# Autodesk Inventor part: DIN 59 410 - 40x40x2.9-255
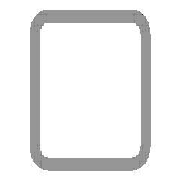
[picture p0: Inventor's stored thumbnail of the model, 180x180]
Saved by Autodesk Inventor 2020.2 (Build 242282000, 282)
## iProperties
Manager: www.cadconsulting.pl
Company: Fabian Stasiak CAD Consulting
_CCFamilyMember: 10
_CCFamilyDisplayName: DIN 59410 (Kwadrat) - Rurki stalowe o przekroju kwadratowym formowane na gorąco
_FrameMemberDoc: Frame Member File
_Version: 15.0.0
_GetPNFromCC: 1
Created: 2015-01
Part Number: DIN 59 410 - 40x40x2.9-255
Material: Stal, miękka
Description: Rurki stalowe o przekroju kwadratowym formowane na gorąco
Document SubType Name: Modellieren
Standard: DIN
Designer: F.Stasiak
Standards Organization: DIN
Language: pl-PL
Size Designation: 40x40x2.9
Categories: <MemberInstance><Categories><Category DisplayName="Kształtowniki konstrukcyjne" InternalName="089c4875-fa83-4c05-b084-43b9cc11f5ed" Mnemonic="GRDR"><CategoryPar
Stock Number: 40x40x2.9
Density: 7.85 g/cm^3
Appearance: Częściowo polerowana
Mass: 818.12 g
Surface Area: 726.927 cm^2
Volume: 104.219 cm^3
Catalog Web Link: www.expertbooks.pl
IsCustomPart: 1
G_L: 255,000 mm
G_W: 40,000 mm
G_H: 40,000 mm
+9123B27D-AADA-494F-B97F-F92D2769A03D+CUTDETAIL1: Wytnij
+8B292EAE-3E6B-4FBF-B364-8C41014E1728+CUTDETAIL2: Wytnij
Author: F.Stasiak
Subject: Zbiór ćwiczeń. Autodesk Inventor 2020. Kurs Professional
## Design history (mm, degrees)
node "Płaszczyzna początkowa"
node "Płaszczyzna końcowa"
sketch "Szkic"
  geometry: L1 (-14.2, 20)-(14.2, 20); L2 (20, 14.2)-(20, -14.2); L3 (14.2, -20)-(-14.2, -20); L4 (-20, -14.2)-(-20, 14.2); L5 (-29.682, 0)-(29.682, 0) reference; L6 (0, -29.682)-(0, 29.682) reference; L7 (-14.2, 17.1)-(14.2, 17.1); L8 (17.1, 14.2)-(17.1, -14.2); L9 (14.2, -17.1)-(-14.2, -17.1); L10 (-17.1, -14.2)-(-17.1, 14.2); A1 r 5.8 centre (-14.2, 14.2) between (-14.2, 20) and (-20, 14.2); A2 r 5.8 centre (14.2, 14.2) between (20, 14.2) and (14.2, 20); A3 r 5.8 centre (14.2, -14.2) between (14.2, -20) and (20, -14.2); A4 r 5.8 centre (-14.2, -14.2) between (-20, -14.2) and (-14.2, -20); A5 r 2.9 centre (-14.2, 14.2) between (-14.2, 17.1) and (-17.1, 14.2); A6 r 2.9 centre (14.2, 14.2) between (17.1, 14.2) and (14.2, 17.1); A7 r 2.9 centre (14.2, -14.2) between (14.2, -17.1) and (17.1, -14.2); A8 r 2.9 centre (-14.2, -14.2) between (-17.1, -14.2) and (-14.2, -17.1); 3 further points
  constraints: 16 end point, 16 point on circle, 8 centre point, 8 tangent, 6 point on line, 4 parallel, 3 equal radius, 3 perpendicular, 1 horizontal, 7 other
  dimensions: "b" = 40 distance of point (-20, 20) point (20, 20); "msp_r" = 5.8 radius of A1 (= 2 x ParT); "d8" = 20 distance between parallel lines of L4 L6 (= d9); "d9" = 20 distance between parallel lines of L3 L5 (= 0.5 x b); "d10" = 2.9 distance between parallel lines of L3 L9 (= ParT)
extrude "Bryła" new body sketch "Szkic" taper "d4" = 0 deg; stored distance "NLG" = 10
node "Driven Length"
  sketch "Sketch2"
    geometry: L1 (0, 0)-(10, 0) reference
    constraints: 2 end point, 1 horizontal
  workplane "Work Plane3"
  sketch "Sketch3"
    geometry: L1 (-2, 5)-(12, 5) reference; L2 (-2, 260)-(12, 260) reference
    dimensions: "d14" = 255 distance between parallel lines of L1 L2 (derived)
node "Płaszczyzna konstrukcyjna4"
feature "Podział1"
node "Płaszczyzna konstrukcyjna5"
feature "Podział2"
body "Solid1"
other parameters: "ParT" = 2.9, "G_OFFSET_START" = -5 [user parameter; used in 1 equation term], "G_OFFSET_END" = -25 [user parameter; used in 1 equation term], "d11" = 5 (= -G_OFFSET_START), "G_L" = 255 (= d14) [user parameter], "B_L" = 285 [user parameter; used in 1 equation term], "d13" = 90 deg
